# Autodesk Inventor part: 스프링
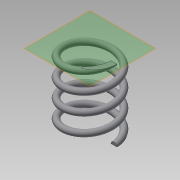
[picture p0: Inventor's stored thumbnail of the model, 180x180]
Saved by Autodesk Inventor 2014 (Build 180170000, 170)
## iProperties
Created: 2015-04
Part Number: 스프링
Material: Generic
Document SubType Name: Modeling
Designer: Administrator
Density: 1 g/cm^3
Appearance: Default
Mass: 0.618586 g
Surface Area: 12.6122 cm^2
Volume: 0.618586 cm^3
Author: Administrator
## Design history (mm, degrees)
sketch "스케치1"
  geometry: L1 (0, 11.5)-(8, 11.5); L2 (8, 11.5)-(8, 0); L3 (8, 0)-(0, 0); L4 (0, 0)-(0, 11.5); C1 r 1 at (8, 0); 1 further point
  constraints: 8 end point, 2 coincident, 2 parallel, 1 centre point, 1 horizontal, 1 perpendicular
  dimensions: "d0" = 16 diameter of L2 L4; "d1" = 11.50049 distance between parallel lines of L1 L3 (derived); "d2" = 2 diameter of C1
feature "코일1" sketch "스케치1" pitch "d3" = 10; turns "d5" = 4; dims "d4" = 11.50049 (= d1), "d6" = 0, angle "d7" = 90 deg, angle "d8" = 90 deg, "d9" = 0, "d10" = 0
sketch "스케치2"
  geometry: L1 (-9, 0)-(-7, 0) reference; 1 further point
  constraints: 1 horizontal alignment
extrude "돌출1" cut sketch "스케치2" stored distance "d11" = 10; taper "d12" = 0 deg
node "작업 평면1"
sketch "스케치3"
  geometry: L1 (9, 0)-(7, 0) reference; 1 further point
  constraints: 1 horizontal alignment
extrude "돌출2" cut sketch "스케치3" stored distance "d13" = 10; taper "d14" = 0 deg
node "솔리드1"
node "절단 모서리 투영1"
node "절단 모서리 투영2"
